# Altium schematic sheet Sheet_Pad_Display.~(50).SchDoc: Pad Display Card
size A4; Date: 08/05/2013; ApprovedBy: Vincenzo Niespolo; CheckedBy: Vincenzo Niespolo; Author: Vincenzo Niespolo; CompanyName: NiespoTech; DrawnBy: Vincenzo Niespolo; Engineer: Vincenzo Niespolo; Organization: NiespoTech; Address1: Viale E. De Amicis n°39; Address2: Imola (BO); Address3: Cell. +39 334 9113322; Address4: e-mail: niespotech@gmail.com; DocumentNumber: 1; Revision: 00; SheetNumber: 1; SheetTotal: 5
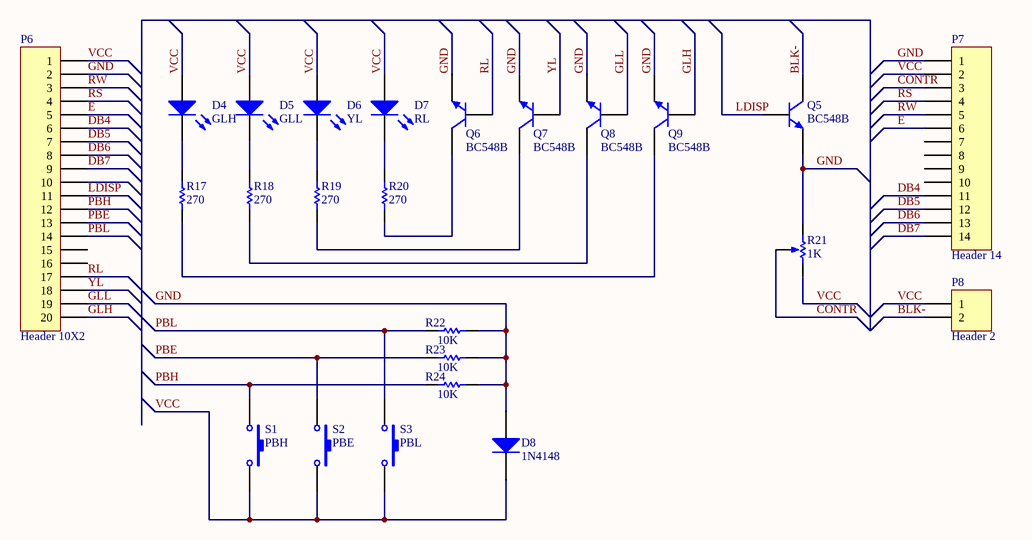
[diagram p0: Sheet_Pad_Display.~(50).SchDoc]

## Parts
D4  GLH  [LED-1]
D5  GLL  [LED-1]
D6  YL  [LED-1]
D7  RL  [LED-1]
D8  1N4148  [DO-35]
P6  Header 10X2  [HDR2X10_CEN]
P7  Header 14  [HDR1X14]
P8  Header 2  [HDR1X2]
Q5  BC548B  [29-04]
Q6  BC548B  [29-04]
Q7  BC548B  [29-04]
Q8  BC548B  [29-04]
Q9  BC548B  [29-04]
R17  270  [AXIAL-0.3]
R18  270  [AXIAL-0.3]
R19  270  [AXIAL-0.3]
R20  270  [AXIAL-0.3]
R21  1K  [VR5]
R22  10K  [AXIAL-0.3]
R23  10K  [AXIAL-0.3]
R24  10K  [AXIAL-0.3]
S1  PBH  [SPST-2]
S2  PBE  [SPST-2]
S3  PBL  [SPST-2]

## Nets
BLK-: P8.2 Q5.1(C)
CONTR: P7.3 R21.3(TAP)
DB4: P6.6 P7.11
DB5: P6.7 P7.12
DB6: P6.8 P7.13
DB7: P6.9 P7.14
E: P6.5 P7.6
GLH: P6.20 Q9.2(B)
GLL: P6.19 Q8.2(B)
GND: D8.1(A) P6.2 P7.1 Q5.3(E) Q6.3(E) Q7.3(E) Q8.3(E) Q9.3(E) R21.1(TOP) R22.1 R23.1 R24.1
LDISP: P6.11 Q5.2(B)
PBE: P6.13 R23.2 S2.1
PBH: P6.12 R24.2 S1.1
PBL: P6.14 R22.2 S3.1
RL: P6.17 Q6.2(B)
RS: P6.4 P7.4
RW: P6.3 P7.5
VCC: D4.1(A) D5.1(A) D6.1(A) D7.1(A) D8.2(K) P6.1 P7.2 P8.1 R21.2(BOT) S1.2 S2.2 S3.2
YL: P6.18 Q7.2(B)
NetD4_2: D4.2(K) R17.2
NetD5_2: D5.2(K) R18.2
NetD6_2: D6.2(K) R19.2
NetD7_2: D7.2(K) R20.2
NetQ6_1: Q6.1(C) R20.1
NetQ7_1: Q7.1(C) R19.1
NetQ8_1: Q8.1(C) R18.1
NetQ9_1: Q9.1(C) R17.1

Not connected (* = marked no-connect by the designer): P6 10 15 16; P7 7 8 9 10

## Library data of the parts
D4-D7 = LED1: Typical RED GaAs LED
D8 = Diode 1N4148: High Conductance Fast Diode
P6 = Header 20: Header, 20-Pin
P7 = Header 14: Header, 14-Pin
P8 = Header 2: Header, 2-Pin
Q5-Q9 = BC548B: Amplifier Transistor NPN Silicon
R17-R20 R22-R24 = Res1: Resistor
R21 = RPot: Potentiometer; Sim Note: Enter the Resistance value and the set point into parameter fields.; Set Position: 0.5
S1-S3 = SW-PB: Switch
